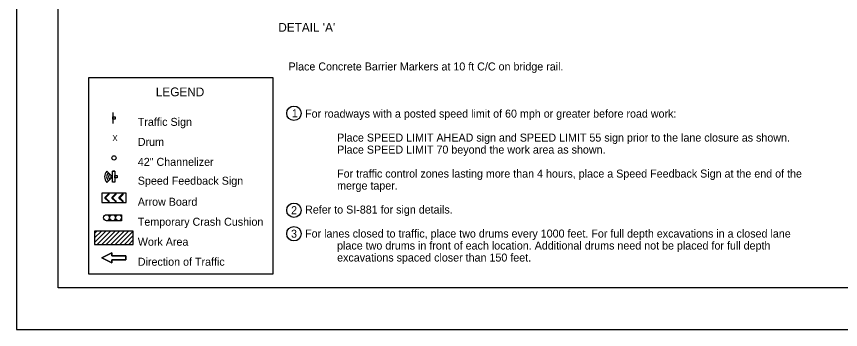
# Model space of a CAD drawing. Extents: x 10133 to 81668, y 4177 to 11018.
# Drawn here: x 24428 to 26486, y 7820 to 8603 of the extents above; entities that cross this region are included whole.
import ezdxf

# ---------------------------------------------------------------- set-up
doc = ezdxf.new("R2010")
doc.units = 0
for name, color, linetype in [('dsnNonPlotable', 7, 'Continuous'), ('dsnStdBlockModified', 7, 'Continuous'), ('dsnStdBorder', 7, 'Continuous'), ('dsnStdLabel', 7, 'Continuous'), ('dsnStdLineWork', 7, 'Continuous'), ('dsnstdModifiedBlock', 7, 'Continuous'), ('Level 1', 7, 'Continuous'), ('Level 2', 7, 'Continuous'), ('SheetBorder', 7, 'Continuous')]:
    doc.layers.add(name, color=color, linetype=linetype)

msp = doc.modelspace()

# ---------------------------------------------------------------- linework, layer by layer
at = {"layer": 'dsnNonPlotable'}
for p, q in [((24669, 8362.5), (24669, 8335)), ((24673.7, 8215.4), (24673.7, 8187.9)), ((24648.8, 8149.8), (24657.6, 8158.7)), ((24666.4, 8149.8), (24675.2, 8158.7)), ((24684, 8149.8), (24692.8, 8158.7)), ((24652.9, 8106.6), (24690.4, 8106.6)), ((24690.4, 8091.6), (24652.9, 8091.6)), ((24690.4, 8106.6), (24690.4, 8091.6)), ((24623.3, 8060.1), (24628.9, 8065.7)), ((24623.3, 8048.8), (24640.3, 8065.7)), ((24623.3, 8037.5), (24651.6, 8065.7)), ((24629.6, 8032.5), (24662.9, 8065.7)), ((24640.9, 8032.5), (24674.2, 8065.7)), ((24652.2, 8032.5), (24685.5, 8065.7)), ((24663.5, 8032.5), (24696.8, 8065.7)), ((24674.9, 8032.5), (24708.1, 8065.7)), ((24686.2, 8032.5), (24719.5, 8065.7)), ((24697.5, 8032.5), (24719.9, 8054.9)), ((24708.8, 8032.5), (24719.9, 8043.6))]:
    msp.add_line(p, q, dxfattribs=at)
for points in [[(24669.1, 8346.1), (24669.1, 8351.7), (24674.7, 8351.7), (24674.7, 8346.1)], [(24668.1, 8187.9), (24668.1, 8215.4), (24673.7, 8215.4), (24673.7, 8187.9)], [(24673.7, 8199), (24673.7, 8204.6), (24679.3, 8204.6), (24679.3, 8199)], [(24701.6, 8160.6), (24641.6, 8160.6), (24641.6, 8137.6), (24701.6, 8137.6)], [(24623.3, 8065.7), (24623.3, 8032.5), (24719.9, 8032.5), (24719.9, 8065.7)], [(24701.3, 8004.1), (24701.3, 7994.1), (24666.3, 7994.1), (24666.3, 7986.6), (24641.3, 7999.1), (24666.3, 8011.6), (24666.3, 8004.1)]]:
    msp.add_lwpolyline(points, close=True, dxfattribs=at)
for points in [[(24659.1, 8157.2), (24659.1, 8157.2), (24650.6, 8149.1), (24659.1, 8141)], [(24676.6, 8157.2), (24676.6, 8157.2), (24668.1, 8149.1), (24676.6, 8141)], [(24694.3, 8157.2), (24694.3, 8157.2), (24685.8, 8149.1), (24694.3, 8141)], [(24657.7, 8139.5), (24657.6, 8139.6), (24648.8, 8148.4), (24648.8, 8148.4)], [(24675.2, 8139.5), (24675.2, 8139.6), (24666.4, 8148.4), (24666.4, 8148.4)], [(24692.9, 8139.5), (24692.8, 8139.6), (24684, 8148.4), (24684, 8148.4)], [(24666.3, 8004.1), (24666.3, 8011.6), (24641.3, 7999.1), (24666.3, 7986.6), (24666.3, 7994.1), (24701.3, 7994.1), (24701.3, 8004.1), (24666.3, 8004.1)]]:
    msp.add_lwpolyline(points, dxfattribs=at)
for centre, radius in [((24671.6, 8248.9), 5.37), ((24671.6, 8248.9), 5.37), ((24652.9, 8099.1), 7.5), ((24652.9, 8099.1), 7.5), ((24667.9, 8099.1), 7.5), ((24667.9, 8099.1), 7.5), ((24682.9, 8099.1), 7.5), ((24682.9, 8099.1), 7.5)]:
    msp.add_circle(centre, radius, dxfattribs=at)
for centre, start, end in [((24658.4, 8157.9), 315.0975, 135.281), ((24675.9, 8157.9), 315.0975, 135.281), ((24693.6, 8157.9), 315.0975, 135.281), ((24649.6, 8149.1), 134.1616, 224.6098), ((24658.4, 8140.3), 226.201, 47.3602), ((24667.1, 8149.1), 134.1616, 224.6098), ((24675.9, 8140.3), 226.201, 47.3602), ((24684.7, 8149.1), 134.1616, 224.6098), ((24693.6, 8140.3), 226.201, 47.3602)]:
    msp.add_arc(centre, 1.03, start, end, dxfattribs=at)
at = {"layer": 'dsnStdBlockModified'}
msp.add_lwpolyline([(24532.5, 9934), (27667.5, 9934), (27667.5, 7924), (24532.5, 7924)], close=True, dxfattribs=at)
at = {"layer": 'dsnStdBorder'}
msp.add_lwpolyline([(24428, 7819.5), (27772, 7819.5), (27772, 10403.5), (24428, 10403.5)], close=True, dxfattribs=at)
at = {"layer": 'dsnStdLabel'}
msp.add_lwpolyline([(24607.5, 8448.9), (24607.5, 7958.6), (25069.4, 7958.6), (25069.4, 8448.9), (24607.5, 8448.9)], dxfattribs=at)
at = {"layer": 'dsnStdLineWork'}
for p, q in [((24653.9, 8215.8), (24668.1, 8201.7)), ((24673.7, 8215.4), (24668.1, 8215.4)), ((24668.1, 8201.7), (24653.9, 8187.5)), ((24673.7, 8187.9), (24668.1, 8187.9))]:
    msp.add_line(p, q, dxfattribs=at)
for radius, start, end in [(20.3, 135.88, 224.0313), (15.3, 136.1665, 223.7159), (10.3, 136.7294, 223.0963), (5.32, 138.7005, 221.2995)]:
    msp.add_arc((24668.5, 8201.7), radius, start, end, dxfattribs=at)
at = {"layer": 'Level 2'}
for centre in [(25121, 8360.4), (25121, 8118), (25121, 8059.2)]:
    msp.add_circle(centre, 18, dxfattribs=at)
at = {"layer": 'SheetBorder'}
msp.add_lwpolyline([(24532.5, 9944), (27667.5, 9944), (27667.5, 7924), (24532.5, 7924)], close=True, dxfattribs=at)

# ---------------------------------------------------------------- texts
at = {"layer": 'dsnNonPlotable'}
for s, height, p in [('LEGEND', 22, (24776.1, 8402.9)), ('Traffic Sign', 20, (24731.1, 8328.9)), ('Drum', 20, (24731.1, 8278.9)), ('42" Channelizer ', 20, (24731.1, 8228.9)), ('Speed Feedback Sign', 20, (24731.1, 8181.7)), ('Arrow Board', 20, (24731.1, 8129.1)), ('Temporary Crash Cushion', 20, (24731.1, 8079.1)), ('Work Area', 20, (24731.1, 8029.1)), ('Direction of Traffic', 20, (24731.1, 7979.1))]:
    msp.add_text(s, height=height, dxfattribs=at).set_placement(p)
msp.add_text('X', height=15, rotation=180, dxfattribs=at).set_placement((24681, 8306.4))
at = {"layer": 'dsnstdModifiedBlock'}
msp.add_text("DETAIL 'A'", height=22, dxfattribs=at).set_placement((25082, 8564.3))
at = {"layer": 'Level 1'}
for s, p in [('Place Concrete Barrier Markers at 10 ft C/C on bridge rail.', (25107.6, 8467.5)), ('For roadways with a posted speed limit of 60 mph or greater before road work:', (25148.9, 8349.6)), ('Place SPEED LIMIT AHEAD sign and SPEED LIMIT 55 sign prior to the lane closure as shown. ', (25228.9, 8289.6)), ('Place SPEED LIMIT 70 beyond the work area as shown.', (25228.9, 8259.6)), ('For traffic control zones lasting more than 4 hours, place a Speed Feedback Sign at the end of the ', (25228.9, 8199.6)), ('merge taper.', (25228.9, 8169.6)), ('Refer to SI-881 for sign details.', (25148.9, 8109.6)), ('For lanes closed to traffic, place two drums every 1000 feet. For full depth excavations in a closed lane ', (25148.9, 8049.6)), ('place two drums in front of each location. Additional drums need not be placed for full depth ', (25228.9, 8019.6)), ('excavations spaced closer than 150 feet.', (25228.9, 7989.6))]:
    msp.add_text(s, height=20, dxfattribs=at).set_placement(p)
at = {"layer": 'Level 2'}
for s, p in [('1', (25115.8, 8350.4)), ('2', (25113.9, 8108)), ('3', (25113.8, 8049.2))]:
    msp.add_text(s, height=20, dxfattribs=at).set_placement(p)

doc.saveas('drawing.dxf')
